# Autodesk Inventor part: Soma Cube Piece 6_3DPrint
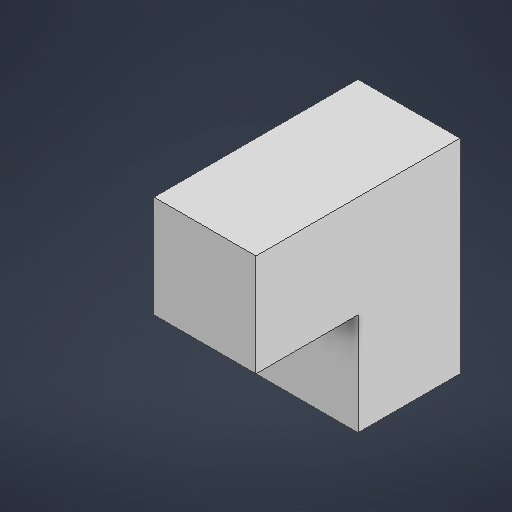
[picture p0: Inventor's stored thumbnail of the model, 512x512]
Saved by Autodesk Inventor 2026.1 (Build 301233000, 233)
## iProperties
Created: 2025-12
Part Number: Soma Cube Piece 6_3DPrint
Material: Generic
Document SubType Name: Modeling
Designer: egberbos000
Density: 1 g/cm^3
Appearance: Default
Author: egberbos000
Part Number: Soma Cube Piece 6
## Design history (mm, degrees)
sketch "Sketch1"
  geometry: L1 (0, 0)-(50.8, 0); L2 (50.8, 0)-(50.8, 25.4); L3 (50.8, 25.4)-(0, 25.4); L4 (0, 25.4)-(0, 0)
  constraints: 8 end point, 2 parallel, 1 horizontal, 1 perpendicular
  dimensions: "d0" = 50.8 distance of L2.end L3.end; "d1" = 25.4 distance of L1.end L2.end
extrude "Extrusion1" new body sketch "Sketch1" distance "d2" = 25.4; taper "d3" = 0 deg
sketch "Sketch2"
  geometry: L1 (50.8, 25.4)-(0, 25.4) reference; L2 (25.4, 25.4)-(50.8, 25.4); L3 (50.8, 25.4)-(50.8, 50.8); L4 (50.8, 50.8)-(25.4, 50.8); L5 (25.4, 50.8)-(25.4, 25.4); 2 further points
  constraints: 8 end point, 2 parallel, 1 horizontal, 1 midpoint, 1 perpendicular
  dimensions: "d4" = 25.4 distance of L2.end L3.end; "d5" = 25.4 distance of L3.end L4.end
extrude "Extrusion2" join sketch "Sketch2" distance "d6" = 25.4; taper "d8" = 0 deg; dims "d7" = 25.4, "d9" = 0
body "Solid1"
